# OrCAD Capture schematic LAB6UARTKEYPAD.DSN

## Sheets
1 4x4 keypad: size A
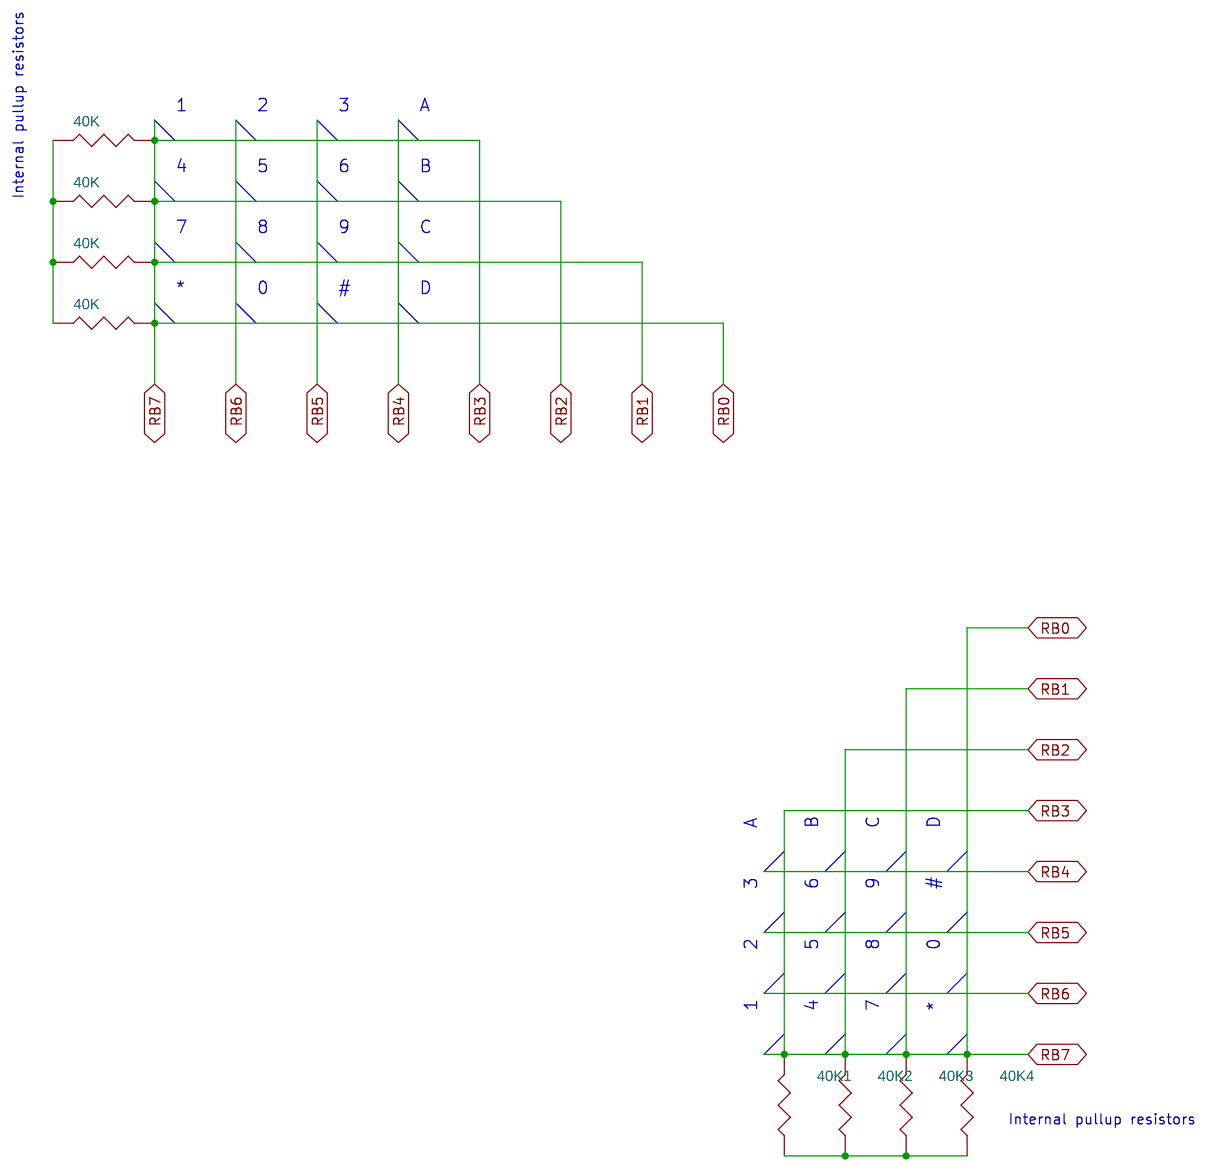
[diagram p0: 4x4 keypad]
2 lab6uart_keypad: size A
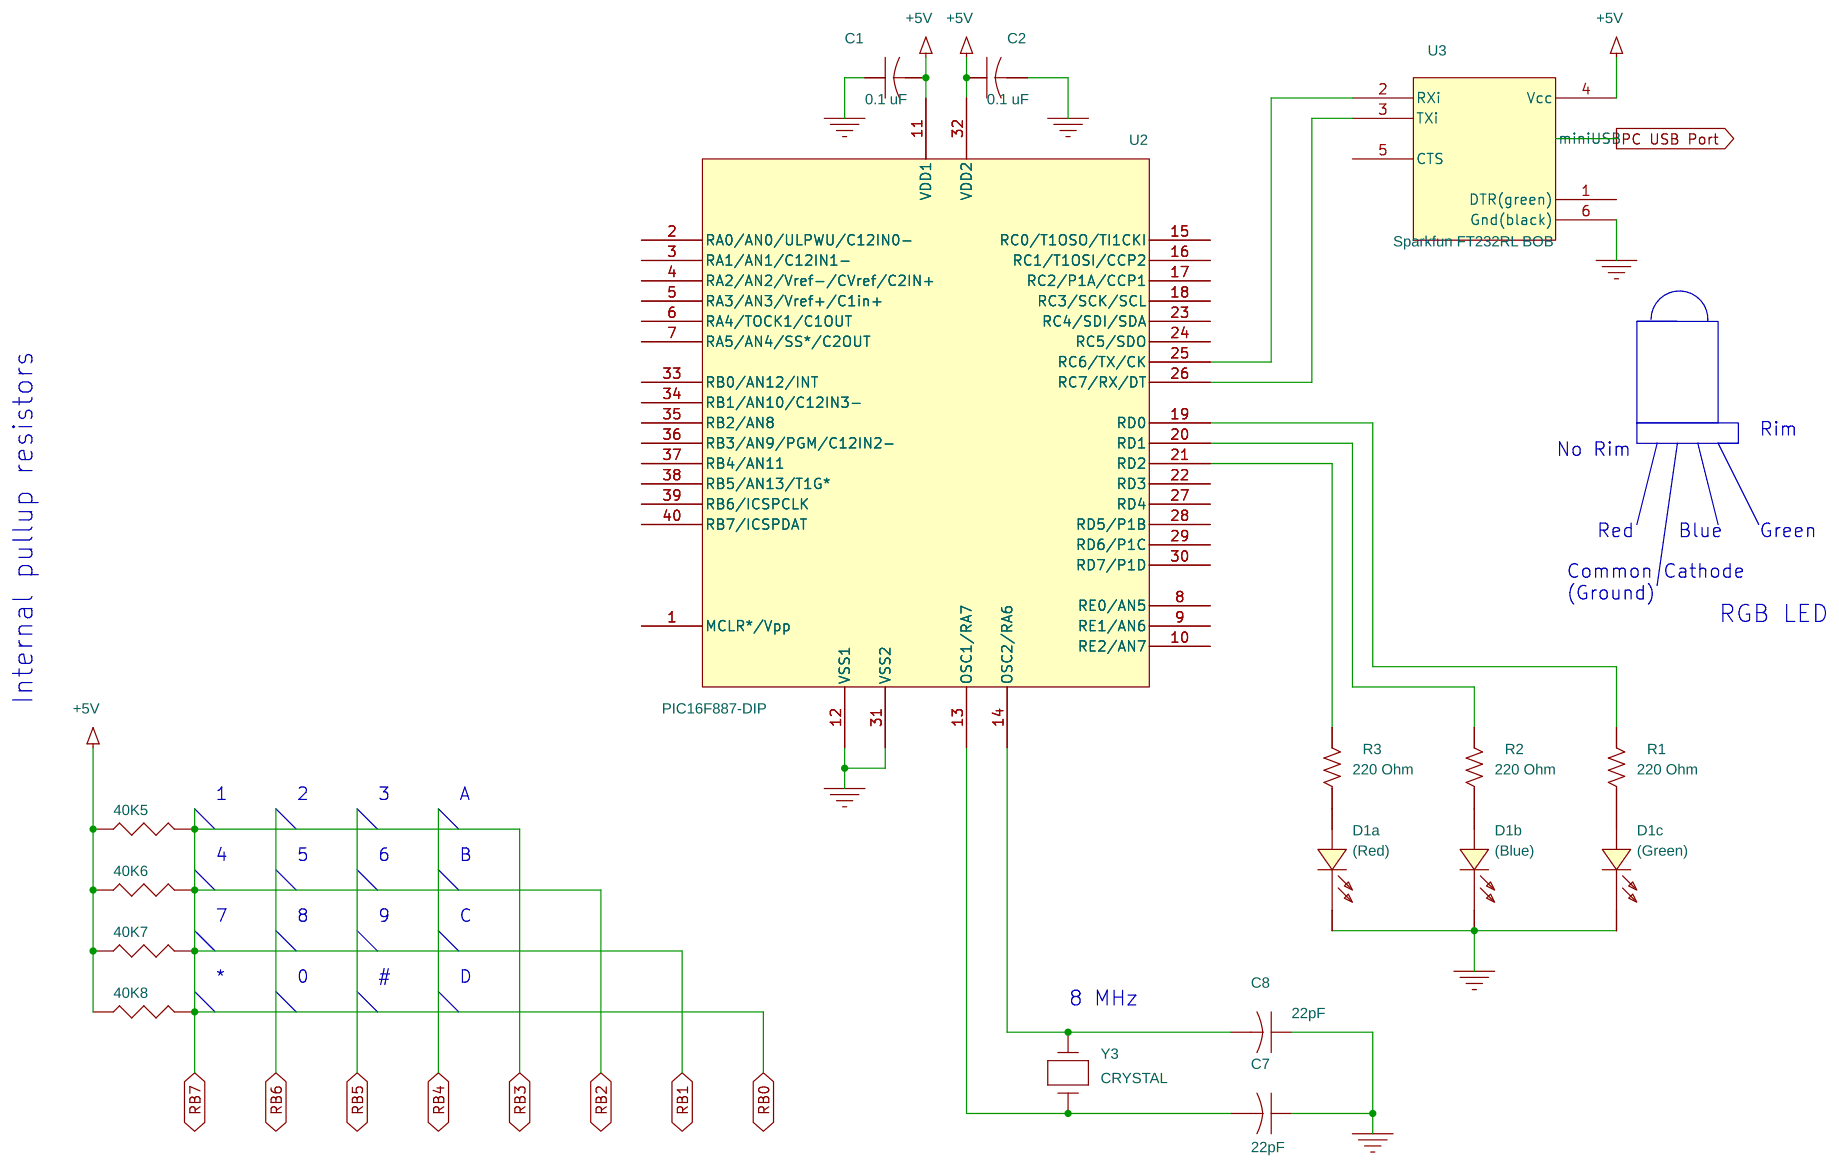
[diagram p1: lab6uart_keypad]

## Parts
sheet 4x4 keypad
40K  RESISTOR
40K1  RESISTOR
40K2  RESISTOR
40K3  RESISTOR
40K4  RESISTOR
40K#2  RESISTOR
40K#3  RESISTOR
40K#4  RESISTOR
sheet lab6uart_keypad
40K5  RESISTOR
40K6  RESISTOR
40K7  RESISTOR
40K8  RESISTOR
(Blue)  D1b
(Green)  D1c
(Red)  D1a
C1  0.1 uF
C2  0.1 uF
C7  22pF
C8  22pF
R1  220 Ohm  [AX/RC05]
R2  220 Ohm  [AX/RC05]
R3  220 Ohm  [AX/RC05]
U2  PIC16F887-DIP
U3  Sparkfun FT232RL BOB
Y3  CRYSTAL

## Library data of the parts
40K 40K1-40K8 40K#2-40K#4 = RESISTOR
(Blue) (Green) (Red) = LED
C1 C2 = C
C7 C8 = CAP
R1-R3 = R
U2 = PIC16F887_0
U3 = FT232RL-BOB_1
Y3 = CRYSTAL

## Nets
+5V: 40K5.1 40K6.1 40K7.1 40K8.1 C1.2 C2.1 U2.11(VDD1) U2.32(VDD2) U3.4(Vcc)
GND: (Blue).2(CATHODE) (Green).2(CATHODE) (Red).2(CATHODE) C1.1 C2.2 C7.1 C8.1 U2.12(VSS1) U2.31(VSS2) U3.6(Gnd(black))
PC USB Port: U3.miniUSB
RB0: 40K.2 40K1.2 40K2.2 40K3.2 40K4.2 40K5.2 40K6.2 40K7.2 40K8.2 40K#2.2 40K#3.2 40K#4.2
N01311: R1.2 U2.19(RD0)
N01327: R2.2 U2.20(RD1)
N01343: R3.2 U2.21(RD2)
N01431: U2.25(RC6/TX/CK) U3.2(RXi)
N01443: U2.26(RC7/RX/DT) U3.3(TXi)
N04449: 40K.1 40K#2.1 40K#3.1 40K#4.1
N06856: 40K1.1 40K2.1 40K3.1 40K4.1
N1033228: C7.2 U2.13(OSC1/RA7) Y3.2
N1033236: C8.2 U2.14(OSC2/RA6) Y3.1
N1033663: (Red).1(ANODE) R3.1
N1033690: (Blue).1(ANODE) R2.1
N1033717: (Green).1(ANODE) R1.1

Not connected (* = marked no-connect by the designer): U2 1(MCLR*/Vpp) 2(RA0/AN0/ULPWU/C12IN0-) 3(RA1/AN1/C12IN1-) 4(RA2/AN2/Vref-/CVref/C2IN+) 5(RA3/AN3/Vref+/C1in+) 6(RA4/TOCK1/C1OUT) 7(RA5/AN4/SS*/C2OUT) 8(RE0/AN5) 9(RE1/AN6) 10(RE2/AN7) 15(RC0/T1OSO/TI1CKI) 16(RC1/T1OSI/CCP2) 17(RC2/P1A/CCP1) 18(RC3/SCK/SCL) 22(RD3) 23(RC4/SDI/SDA) 24(RC5/SDO) 27(RD4) 28(RD5/P1B) 29(RD6/P1C) 30(RD7/P1D) 33(RB0/AN12/INT) 34(RB1/AN10/C12IN3-) 35(RB2/AN8) 36(RB3/AN9/PGM/C12IN2-) 37(RB4/AN11) 38(RB5/AN13/T1G*) 39(RB6/ICSPCLK) 40(RB7/ICSPDAT); U3 1(DTR(green)) 5(CTS)

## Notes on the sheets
sheet 1
- 1
- 2
- 3
- A
- 4
- 5
- 6
- B
- Internal pullup resistors
- 7
- 8
- 9
- C
- *
- 0
- #
- D
- A
- B
- C
- D
- 3
- 6
- 9
- #
- 2
- 5
- 8
- 0
- 1
- 4
- 7
- *
- Internal pullup resistors
sheet 2
- Rim
- No Rim
- Red
- Blue
- Green
- Common Cathode
   (Ground)
- RGB LED
- Internal pullup resistors
- 1
- 2
- 3
- A
- 4
- 5
- 6
- B
- 7
- 8
- 9
- C
- *
- 0
- #
- D
- 8 MHz
